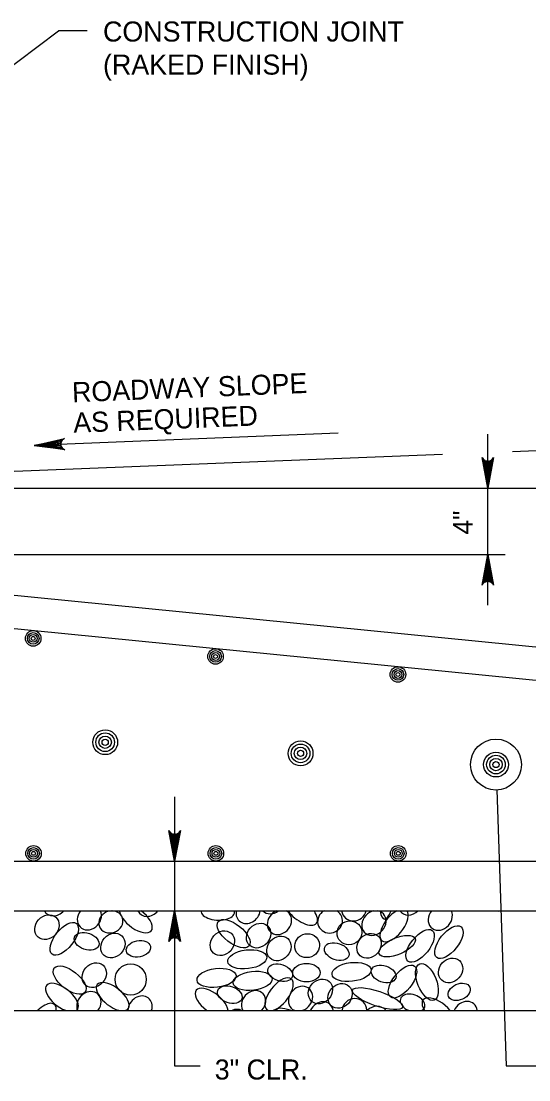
# Model space of a CAD drawing. Extents: x 638167 to 640248, y 296544 to 298920.
# Drawn here: x 638403.6 to 638481.4, y 298060.6 to 298222.8 of the extents above; entities that cross this region are included whole.
import ezdxf

# ---------------------------------------------------------------- set-up
doc = ezdxf.new("R2010")
doc.units = 0
doc.layers.add('1', color=7, linetype='Continuous')
doc.layers.add('50', color=7, linetype='Continuous')

# ---------------------------------------------------------------- blocks, each defined once
blk = doc.blocks.new('BAR')
at = {"layer": '50'}
for radius in [2, 1.5, 1, 0.5]:
    blk.add_circle((0, 0), radius, dxfattribs=at)

msp = doc.modelspace()

# ---------------------------------------------------------------- linework, layer by layer
at = {"layer": '1'}
for p, q in [((638396.91, 298211.96), (638409.32, 298221.26)), ((638413.73, 298221.26), (638409.32, 298221.26)), ((638586.78, 298161.11), (638478.9, 298156.79)), ((638452.16, 298159.63), (638405.58, 298157.76)), ((638475.1, 298133.3), (638475.1, 298159.48)), ((638468.17, 298156.36), (638397.47, 298153.54)), ((638341.35, 298151.22), (638571.51, 298151.22)), ((638339.46, 298141.06), (638583.3, 298116.92)), ((638341.35, 298141.06), (638477.78, 298141.06)), ((638297.78, 298140.07), (638578.22, 298112.32)), ((638427.12, 298103.93), (638427.12, 298062.68)), ((638476.48, 298104.97), (638477.91, 298062.68)), ((638291.5, 298094.06), (638578.22, 298094.06)), ((638288.02, 298086.44), (638583.3, 298086.44)), ((638273.02, 298071.2), (638598.3, 298071.2)), ((638427.12, 298062.68), (638431.03, 298062.68)), ((638477.91, 298062.68), (638483.2, 298062.68))]:
    msp.add_line(p, q, dxfattribs=at)
for points in [[(638405.58, 298157.76), (638410.24, 298158.83), (638410.07, 298158.7), (638409.89, 298158.57), (638409.8, 298158.4), (638409.72, 298158.24), (638409.7, 298158.09), (638409.68, 298157.93), (638409.71, 298157.77), (638409.74, 298157.61), (638409.84, 298157.46), (638409.94, 298157.31), (638410.13, 298157.19), (638410.31, 298157.07), (638405.58, 298157.76), (638410.13, 298157.19), (638409.94, 298157.31), (638405.58, 298157.76), (638409.84, 298157.46), (638409.74, 298157.61), (638405.58, 298157.76), (638409.71, 298157.77), (638409.68, 298157.93), (638405.58, 298157.76), (638409.7, 298158.09), (638409.72, 298158.24), (638405.58, 298157.76), (638409.8, 298158.4), (638409.89, 298158.57), (638405.58, 298157.76), (638410.07, 298158.7)], [(638475.1, 298151.22), (638474.22, 298155.91), (638474.35, 298155.73), (638474.47, 298155.55), (638474.63, 298155.46), (638474.79, 298155.36), (638474.94, 298155.34), (638475.1, 298155.31), (638475.26, 298155.34), (638475.42, 298155.36), (638475.57, 298155.46), (638475.73, 298155.55), (638475.86, 298155.73), (638475.98, 298155.91), (638475.1, 298151.22), (638475.86, 298155.73), (638475.73, 298155.55), (638475.1, 298151.22), (638475.57, 298155.46), (638475.42, 298155.36), (638475.1, 298151.22), (638475.26, 298155.34), (638475.1, 298155.31), (638475.1, 298151.22), (638474.94, 298155.34), (638474.79, 298155.36), (638475.1, 298151.22), (638474.63, 298155.46), (638474.47, 298155.55), (638475.1, 298151.22), (638474.35, 298155.73)], [(638475.1, 298141.06), (638475.98, 298136.36), (638475.86, 298136.54), (638475.73, 298136.72), (638475.57, 298136.81), (638475.42, 298136.91), (638475.26, 298136.93), (638475.1, 298136.96), (638474.94, 298136.93), (638474.79, 298136.91), (638474.63, 298136.81), (638474.47, 298136.72), (638474.35, 298136.54), (638474.22, 298136.36), (638475.1, 298141.06), (638474.35, 298136.54), (638474.47, 298136.72), (638475.1, 298141.06), (638474.63, 298136.81), (638474.79, 298136.91), (638475.1, 298141.06), (638474.94, 298136.93), (638475.1, 298136.96), (638475.1, 298141.06), (638475.26, 298136.93), (638475.42, 298136.91), (638475.1, 298141.06), (638475.57, 298136.81), (638475.73, 298136.72), (638475.1, 298141.06), (638475.86, 298136.54)], [(638427.12, 298094.06), (638426.24, 298098.76), (638426.36, 298098.58), (638426.49, 298098.4), (638426.64, 298098.31), (638426.8, 298098.21), (638426.96, 298098.19), (638427.12, 298098.16), (638427.27, 298098.19), (638427.43, 298098.21), (638427.59, 298098.31), (638427.75, 298098.4), (638427.87, 298098.58), (638428, 298098.76), (638427.12, 298094.06), (638427.87, 298098.58), (638427.75, 298098.4), (638427.12, 298094.06), (638427.59, 298098.31), (638427.43, 298098.21), (638427.12, 298094.06), (638427.27, 298098.19), (638427.12, 298098.16), (638427.12, 298094.06), (638426.96, 298098.19), (638426.8, 298098.21), (638427.12, 298094.06), (638426.64, 298098.31), (638426.49, 298098.4), (638427.12, 298094.06), (638426.36, 298098.58)], [(638427.12, 298086.44), (638428, 298081.75), (638427.87, 298081.93), (638427.75, 298082.11), (638427.59, 298082.2), (638427.43, 298082.3), (638427.27, 298082.32), (638427.12, 298082.35), (638426.96, 298082.32), (638426.8, 298082.3), (638426.64, 298082.2), (638426.49, 298082.11), (638426.36, 298081.93), (638426.24, 298081.75), (638427.12, 298086.44), (638426.36, 298081.93), (638426.49, 298082.11), (638427.12, 298086.44), (638426.64, 298082.2), (638426.8, 298082.3), (638427.12, 298086.44), (638426.96, 298082.32), (638427.12, 298082.35), (638427.12, 298086.44), (638427.27, 298082.32), (638427.43, 298082.3), (638427.12, 298086.44), (638427.59, 298082.2), (638427.75, 298082.11), (638427.12, 298086.44), (638427.87, 298081.93)]]:
    msp.add_lwpolyline(points, dxfattribs=at)
for centre, radius in [((638476.35, 298108.86), 3.9), ((638420.39, 298075.94), 2.39)]:
    msp.add_circle(centre, radius, dxfattribs=at)
for centre, major_axis, ratio in [((638407.56, 298083.94), (1.35, 1.52), 0.844245), ((638410.21, 298082.16), (-1.86, -2.36), 0.479042), ((638436.16, 298082.94), (-2.36, 1.86), 0.479042), ((638439.99, 298082.65), (1.35, 1.52), 0.844245), ((638453.9, 298083.09), (-1.78, -0.71), 0.948581), ((638469.14, 298081.65), (-1.86, -2.36), 0.479042), ((638413.64, 298081.77), (1.85, -0.65), 0.646802), ((638417.67, 298081.12), (1.35, 1.52), 0.844245), ((638434.43, 298081.48), (1.35, 1.52), 0.844245), ((638443.09, 298080.69), (1.35, 1.52), 0.844245), ((638447.42, 298081.11), (-1.78, -0.71), 0.948581), ((638456.9, 298081.09), (1.35, 1.52), 0.844245), ((638461.21, 298081.03), (2.75, 1.17), 0.422273), ((638464.73, 298081.08), (-1.86, -2.36), 0.479042), ((638421.58, 298080.64), (1.85, 0.37), 0.666084), ((638451.96, 298080.21), (1.85, -0.65), 0.646802), ((638438.24, 298079.02), (-2.99, -0.36), 0.479042), ((638469.39, 298077.32), (1.35, 1.52), 0.844245), ((638411.04, 298075.83), (-2.36, 1.86), 0.479042), ((638414.8, 298076.59), (1.35, 1.52), 0.844245), ((638433.54, 298076.17), (-2.99, -0.36), 0.479042), ((638443.29, 298076.96), (1.85, -0.65), 0.646802), ((638447.32, 298076.98), (2.11, 0), 0.671766), ((638454.22, 298077.08), (-2.99, -0.36), 0.479042), ((638459.14, 298076.78), (1.85, -0.65), 0.646802), ((638462.03, 298075.61), (-1.86, -2.36), 0.479042), ((638465.78, 298075.56), (1.12, -2.79), 0.479042), ((638439.07, 298075.72), (-2.99, -0.36), 0.479042), ((638449.45, 298074.1), (1.35, 1.52), 0.844245), ((638435.57, 298073.6), (1.85, -0.65), 0.646802), ((638452.47, 298073.41), (1.35, 1.52), 0.844245), ((638458.2, 298072.99), (3.84, -1.3), 0.282192), ((638470.72, 298074.03), (1.62, 0.73), 0.687276)]:
    msp.add_ellipse(centre, major_axis=major_axis, ratio=ratio, dxfattribs=at)
for centre, major_axis, ratio, start_param, end_param in [((638408.84, 298087.56), (1.35, 1.52), 0.844245, 2.840874, 4.729965), ((638414.06, 298085.42), (1.35, 1.52), 0.844245, 1.646659, 5.92418), ((638417.35, 298084.75), (-1.76, -0.7), 0.87402, 4.347672, 10.501851), ((638421.18, 298085.25), (-2.36, 1.86), 0.479042, 0.443803, 4.744324), ((638423.19, 298087.49), (1.35, 1.52), 0.844245, 2.798262, 4.772577), ((638433.73, 298086.32), (2.57, -0.11), 0.504072, 3.123827, 6.463685), ((638438.39, 298086.39), (1.35, 1.52), 0.844245, 2.187172, 5.383667), ((638442.08, 298087.89), (1.35, 1.52), 0.844245, 3.07937, 4.491469), ((638443.18, 298084.71), (1.35, 1.52), 0.844245, 1.061779, 6.50906), ((638446.5, 298086.42), (-2.36, 1.86), 0.479042, 1.014341, 4.173787), ((638450.93, 298084.88), (-1.78, -0.71), 0.948581, 4.858014, 10.05193), ((638454.59, 298086.73), (-1.78, -0.71), 0.948581, 6.041055, 8.868889), ((638457.65, 298084.57), (1.35, 1.52), 0.844245, 0.812597, 6.758242), ((638460.75, 298084.21), (-1.86, -2.36), 0.479042, 3.984367, 9.301958), ((638459.83, 298089.19), (0.61, 4.01), 0.282192, 2.36721, 4.002176), ((638463.22, 298087.7), (1.35, 1.52), 0.844245, 2.937326, 4.633513), ((638467.81, 298085.38), (1.35, 1.52), 0.844245, 1.619643, 5.951196), ((638473.78, 298088.95), (-1.86, -2.36), 0.479042, 0.238343, 0.481611), ((638477.03, 298088.32), (1.35, 1.52), 0.844245, 3.627473, 3.943366), ((638443.12, 298073.65), (-1.86, -2.36), 0.479042, 0.613344, 6.389796), ((638409.85, 298073.17), (-2.36, 1.86), 0.479042, 3.037298, 8.434015), ((638417.63, 298073.3), (-2.36, 1.86), 0.479042, 2.873239, 8.598074), ((638432.78, 298072.42), (-2.36, 1.86), 0.479042, 3.57213, 7.899183), ((638446.41, 298072.98), (1.35, 1.52), 0.844245, 4.147339, 9.706685), ((638413.99, 298072.18), (1.35, 1.52), 0.844245, 4.815265, 9.038759), ((638421.83, 298071.5), (1.35, 1.52), 0.844245, 5.200099, 8.653925), ((638439.21, 298072.33), (1.35, 1.52), 0.844245, 4.720434, 9.133591), ((638454.66, 298071.16), (-1.78, -0.71), 0.948581, 2.768835, 5.857924), ((638463.57, 298072.32), (1.85, -0.65), 0.646802, 5.825434, 10.881517), ((638467.54, 298070.94), (-2.36, 1.86), 0.479042, 4.285286, 7.186027), ((638406.82, 298069.76), (-1.86, -2.36), 0.479042, 2.538262, 4.464878), ((638436.37, 298069.45), (1.35, 1.52), 0.844245, 0.243434, 1.04422), ((638446.26, 298069.33), (3.55, -1.95), 0.282192, 2.12602, 3.204967), ((638449.56, 298070.61), (1.35, 1.52), 0.844245, 5.676034, 8.17799), ((638458.04, 298069.99), (-1.78, -0.71), 0.948581, 3.464469, 5.16229), ((638471.63, 298070.66), (1.35, 1.52), 0.844245, 5.644884, 8.209141)]:
    msp.add_ellipse(centre, major_axis=major_axis, ratio=ratio, start_param=start_param, end_param=end_param, dxfattribs=at)

# ---------------------------------------------------------------- block references
at = {"layer": '1', "xscale": 0.5953136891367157, "yscale": 0.5953136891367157, "rotation": -90.00000000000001}
for p in [(638405.45, 298128.19), (638433.39, 298125.42), (638461.33, 298122.66), (638405.5, 298095.25), (638433.44, 298095.25), (638461.38, 298095.25)]:
    msp.add_blockref('BAR', p, dxfattribs=at)
at = {"layer": '1', "xscale": 0.9524673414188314, "yscale": 0.9524673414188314}
for p in [(638416.48, 298112.28), (638446.41, 298110.57), (638476.35, 298108.86)]:
    msp.add_blockref('BAR', p, dxfattribs=at)

# ---------------------------------------------------------------- texts
at = {"layer": '1'}
for s, p in [('CONSTRUCTION JOINT', (638416.15, 298219.64)), ('(RAKED FINISH)', (638416.15, 298214.57)), ('3" CLR.', (638433.26, 298060.6))]:
    msp.add_text(s, height=3.072, dxfattribs=at).set_placement(p)
for s, height, rotation, p in [('ROADWAY SLOPE', 3.072, 2.2906, (638411.46, 298164.36)), ('AS REQUIRED', 3.072, 2.2906, (638411.64, 298159.69)), ('4"', 3, 90, (638472.78, 298144.11))]:
    msp.add_text(s, height=height, rotation=rotation, dxfattribs=at).set_placement(p)

doc.saveas('drawing.dxf')
